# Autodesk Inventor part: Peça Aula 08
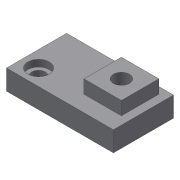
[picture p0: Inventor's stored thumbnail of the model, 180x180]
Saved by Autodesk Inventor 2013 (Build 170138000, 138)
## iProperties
Created: 2012-12
Part Number: Peça Aula 08
Material: Genérico
Document SubType Name: Modeling
Designer: Daniel Severino
Density: 1 g/cm^3
Author: Daniel Severino
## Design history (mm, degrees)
sketch "Esboço1"
  geometry: L1 (0, 0)-(0, 45); L2 (0, 45)-(80, 45); L3 (80, 45)-(80, 0); L4 (80, 0)-(0, 0); C1 r 5 at (12, 12)
  constraints: 8 end point, 2 vertical, 1 centre point, 1 horizontal
  dimensions: "d0" = 45 distance of L1.start L1.end; "d1" = 80 distance of L1.end L2.end; "d2" = 10 diameter of C1; "d3" = 12 distance from line of L4 C1.centre; "d4" = 12 distance from line of C1.centre L1
extrude "Ext Base/Furo" new body sketch "Esboço1" distance "d5" = 15; taper "d6" = 0 deg
sketch "Esboço2"
  geometry: L1 (80, 0)-(80, 45) reference; L2 (80, 45)-(0, 45) reference; L3 (46, 40)-(46, 12); L4 (46, 12)-(74, 12); L5 (74, 12)-(74, 40); L6 (74, 40)-(46, 40)
  constraints: 8 end point, 2 horizontal, 2 vertical
  dimensions: "d7" = 28 distance of L3.start L3.end (= d9); "d9" = 28 distance of L5.end L3.start; "d10" = 5 distance between parallel lines of L6 L2; "d11" = 6 distance between parallel lines of L1 L5
extrude "Extrusão2" join sketch "Esboço2" distance "d12" = 10; taper "d13" = 0 deg
sketch "Esboço3"
  geometry: L1 (46, 40)-(74, 12); C1 r 6 at (60, 26); 1 further point
  constraints: 2 end point, 1 centre point, 1 midpoint
  dimensions: "d14" = 12 diameter of C1
extrude "Furo Superior" cut sketch "Esboço3" stored distance "d17" = 30; taper "d18" = 0 deg
sketch "Esboço4"
  geometry: C1 r 5 at (12, 12) reference; C2 r 8 at (12, 12)
  constraints: 1 centre point, 1 coincident
  dimensions: "d20" = 16 diameter of C2
extrude "Extrusão4" cut sketch "Esboço4" distance "d22" = 5; taper "d23" = 0 deg
sketch "Esboço5"
  geometry: L1 (-74, 12)-(-74, 40) reference; L2 (-74, 40)-(-46, 40) reference; L3 (-46, 40)-(-46, 12) reference; L4 (-46, 12)-(-74, 12) reference; C1 r 6 at (-60, 26) reference
extrude "Extrusão5" join sketch "Esboço5" distance "d24" = 6; taper "d25" = 0 deg
node "Sólido1"
